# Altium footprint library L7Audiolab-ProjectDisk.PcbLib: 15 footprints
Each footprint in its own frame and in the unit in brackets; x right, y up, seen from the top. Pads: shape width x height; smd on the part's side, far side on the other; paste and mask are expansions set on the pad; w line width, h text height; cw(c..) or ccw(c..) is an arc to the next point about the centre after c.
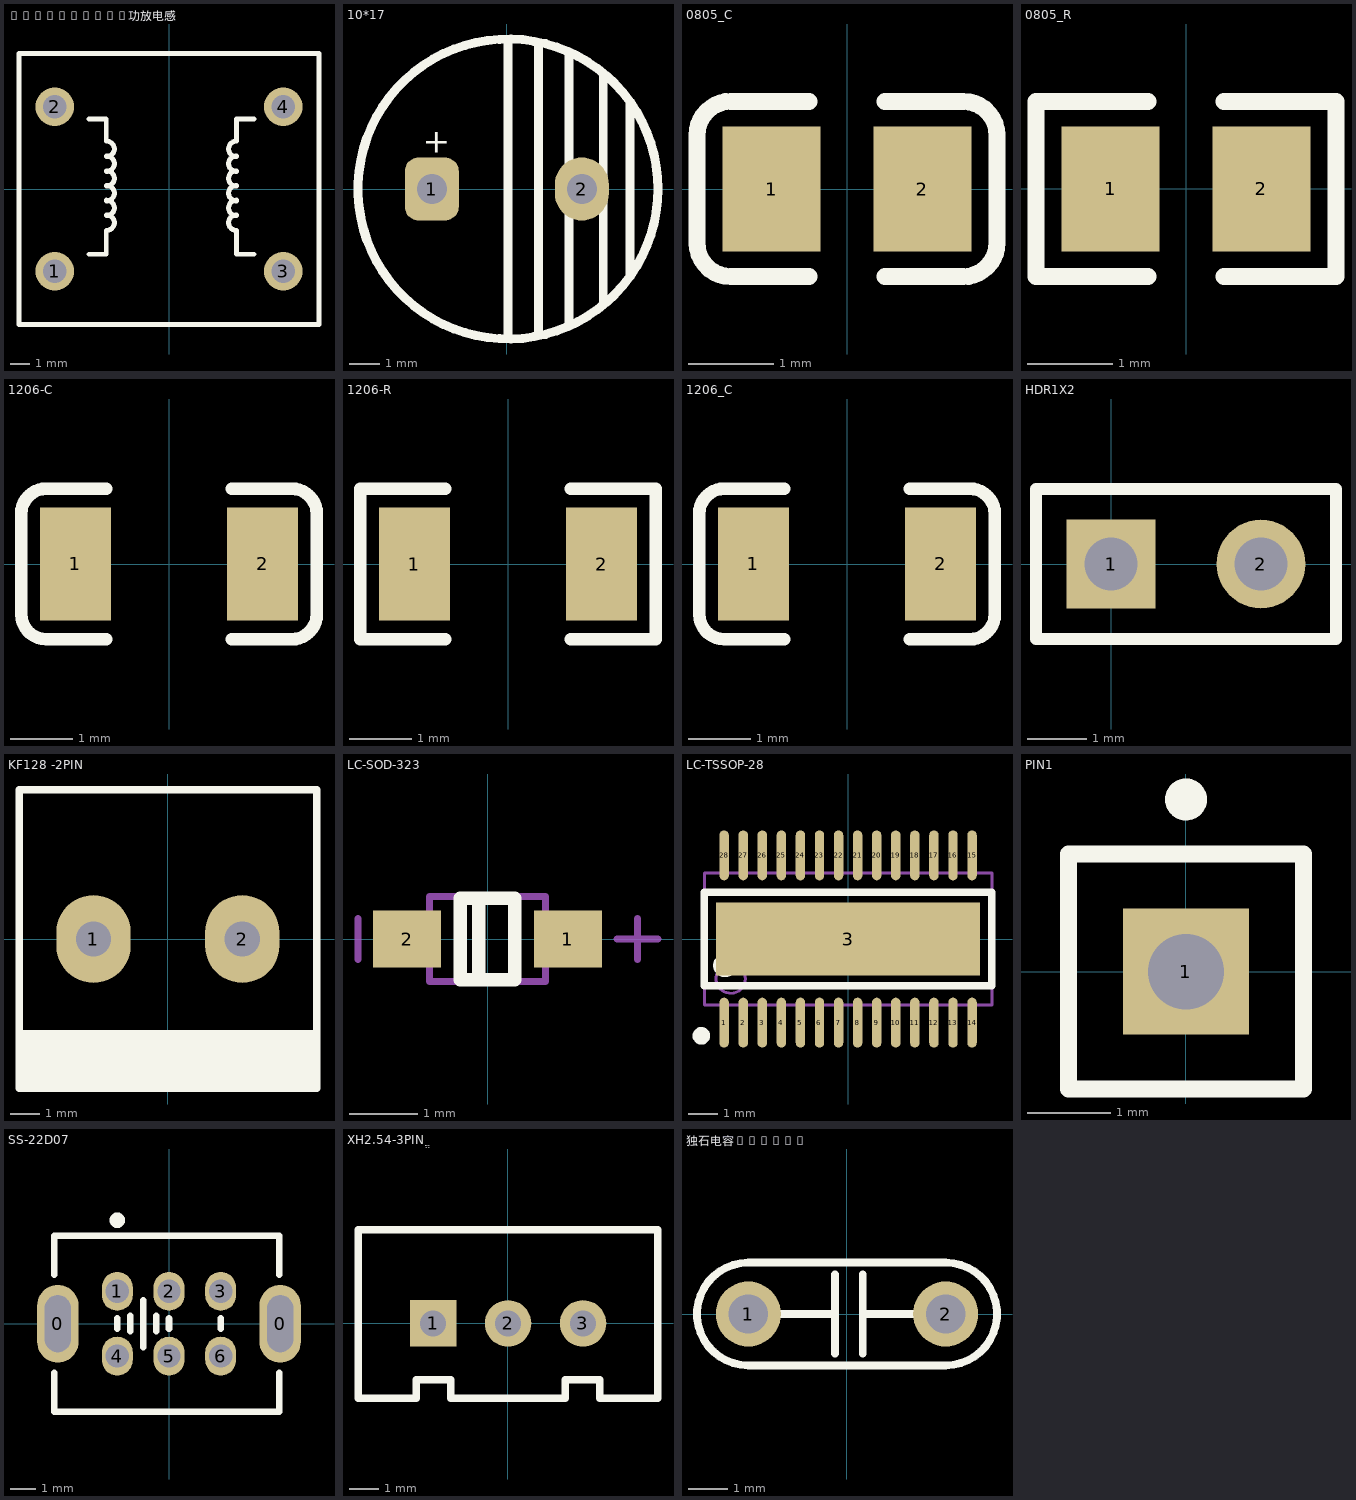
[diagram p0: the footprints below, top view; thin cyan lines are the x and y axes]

## 7W14A-100M功放电感 [mm]
pads (4):
  round 2 hole 1.2: 1(-5.9,-4.25) 2(-5.9,4.25) 3(5.9,-4.25) 4(5.9,4.25)
Top Overlay:
  lines w0.254: -4.129,-3.373 -3.24,-3.373 -3.24,-2.23 ; -4.129,3.612 -3.24,3.612 -3.24,2.469 cw(c-3.223,2.069) -3.242,1.67 ; -3.242,-2.14 ccw(c-3.223,-1.741) -3.24,-1.341 ; -3.242,-1.378 ccw(c-3.223,-0.979) -3.24,-0.579 ; -3.242,-0.616 ccw(c-3.223,-0.217) -3.24,0.183 ; -3.242,0.146 ccw(c-3.223,0.545) -3.24,0.945 ; -3.242,0.908 ccw(c-3.223,1.307) -3.24,1.707 ; 3.494,-2.23 3.494,-3.373 4.383,-3.373 ; 3.494,-1.341 ccw(c3.477,-1.741) 3.496,-2.14 ; 3.494,-0.579 ccw(c3.477,-0.979) 3.496,-1.378 ; 3.494,0.183 ccw(c3.477,-0.217) 3.496,-0.616 ; 3.494,0.945 ccw(c3.477,0.545) 3.496,0.146 ; 3.494,1.707 ccw(c3.477,1.307) 3.496,0.908 ; 3.496,1.67 cw(c3.477,2.069) 3.494,2.469 3.494,3.612 4.383,3.612 ; -7.75,-7 7.75,-7 7.75,7 -7.75,7 -7.75,-7

## 10*17 [mm] "插件电容50V/470UF"
height 1.14
pads (2):
  rrect50% 1.8x2.1 hole 1: 1(-2.5,0)
  oval 1.8x2.1 hole 1: 2(2.5,0)
Top Overlay:
  circle w0.3: c0.04,0 r5
  lines w0.3: 0.04,-4.974 0.04,4.956 ; 1.056,-4.826 1.056,4.836 ; 2.072,-4.536 2.072,4.572 ; 3.215,-3.804 3.215,3.84 ; 4.104,-2.921 4.104,2.886
  text "+" at -2.802,1.2 h0.8

## 0805_C [mm]
height 4.55
pads (2):
  rect 1.16x1.47 smd: 1(-0.89,0) 2(0.89,0)
Top Overlay:
  lines w0.2: -0.45,-1.035 -1.37,-1.035 cw(c-1.37,-0.635) -1.77,-0.635 -1.77,0.635 cw(c-1.37,0.635) -1.37,1.035 -0.45,1.035 ; 0.45,-1.035 1.37,-1.035 ccw(c1.37,-0.635) 1.77,-0.635 1.77,0.635 ccw(c1.37,0.635) 1.37,1.035 0.45,1.035
3D body: height 0.77, standoff -0.01, extent -1,-0.625 1.001,0.625

## 0805_R [mm]
pads (2):
  rect 1.16x1.47 smd: 1(-0.89,0) 2(0.89,0)
Top Overlay:
  lines w0.2: -0.45,-1.035 -1.77,-1.035 -1.77,1.035 -0.45,1.035 ; 0.45,-1.035 1.77,-1.035 1.77,1.035 0.45,1.035
3D body: height 0.49, standoff -0.01, extent -0.997,-0.625 1.003,0.625

## 1206-C [mm]
pads (2):
  rect 1.13x1.8 smd: 1(-1.49,0) 2(1.49,0)
Top Overlay:
  lines w0.2: -1,-1.2 -1.955,-1.2 cw(c-1.955,-0.8) -2.355,-0.8 -2.355,0.8 cw(c-1.955,0.8) -1.955,1.2 -1,1.2 ; 1,-1.2 1.955,-1.2 ccw(c1.955,-0.8) 2.355,-0.8 2.355,0.8 ccw(c1.955,0.8) 1.955,1.2 1,1.2
3D body: height 1, standoff 0, extent -1.602,-0.813 1.598,0.787

## 1206-R [mm] "1206贴片电阻"
height 1.14
pads (2):
  rect 1.13x1.8 smd: 1(-1.49,0) 2(1.49,0)
Top Overlay:
  lines w0.2: -1,-1.2 -2.355,-1.2 -2.355,1.2 -1,1.2 ; 1,-1.2 2.355,-1.2 2.355,1.2 1,1.2
3D body: height 0.85, standoff 0, extent -1.7,-0.864 1.65,0.866

## 1206_C [mm]
pads (2):
  rect 1.13x1.8 smd: 1(-1.49,0) 2(1.49,0)
Top Overlay:
  lines w0.2: -1,-1.2 -1.955,-1.2 cw(c-1.955,-0.8) -2.355,-0.8 -2.355,0.8 cw(c-1.955,0.8) -1.955,1.2 -1,1.2 ; 1,-1.2 1.955,-1.2 ccw(c1.955,-0.8) 2.355,-0.8 2.355,0.8 ccw(c1.955,0.8) 1.955,1.2 1,1.2
3D body: height 1, standoff 0, extent -1.602,-0.813 1.598,0.787

## HDR1X2 [mm] "Connector; Header; 2 Position"
height 1.14
pads (2):
  rect 1.5x1.5 hole 0.9: 1(0,0)
  round 1.5 hole 0.9: 2(2.54,0)
Top Overlay:
  lines w0.2: -1.27,-1.27 3.81,-1.27 3.81,1.27 -1.27,1.27 -1.27,-1.27

## KF128 -2PIN [mm] "5.08螺钉式PCB端子"
height 4.55
pads (2):
  oval 2.54x3 hole 1.2: 1(-2.54,0) 2(2.54,0)
Top Overlay:
  rectangle: -5.084,-5.04 5.162,-3.306
  lines w0.254: -5.08,5.1 -5.08,-5.1 5.08,-5.1 5.08,5.1 -5.078,5.1 ; -5.006,5.1 -4.982,5.1 ; -4.977,-4.423 -3.797,-3.243 ; -4.977,-3.243 5.05,-3.243 ; -3.726,-3.243 -3.721,-3.243 ; -3.652,-4.495 -2.4,-3.243 ; -2.331,-4.495 -1.079,-3.243 ; -1.112,-4.495 0.14,-3.243 ; 0.184,-4.495 1.435,-3.243 ; 1.384,-4.488 2.629,-3.243 ; 2.629,-4.488 3.873,-3.243

## LC-SOD-323 [mm]
height 1.14
pads (2):
  rect 1x0.83 smd: 1(1.18,0) 2(-1.18,0)
Top Overlay:
  lines w0.2: -0.13,-0.6 -0.13,0.6 ; -0.4,-0.6 0.4,-0.6 0.4,0.6 -0.4,0.6 -0.4,-0.6
Mechanical 13:
  lines w0.1: -0.85,-0.625 0.85,-0.625 0.85,0.625 -0.85,0.625 -0.85,-0.625
Mechanical 15:
  lines w0.1: -1.9,-0.3 -1.9,0.3 ; 1.9,0 2.5,0 ; 2.2,-0.3 2.2,0.3
3D body: height 1.1, standoff 0, extent -1.35,-0.625 1.35,0.625

## LC-TSSOP-28 [mm]
height 1.14
pads (29):
  oval 0.32x1.7 smd: 1(-4.225,-2.85) 2(-3.575,-2.85) 3(-2.925,-2.85) 4(-2.275,-2.85) 5(-1.625,-2.85) 6(-0.975,-2.85) 7(-0.325,-2.85) 8(0.325,-2.85) 9(0.975,-2.85) 10(1.625,-2.85) 11(2.275,-2.85) 12(2.925,-2.85) 13(3.575,-2.85) 14(4.225,-2.85) 15(4.225,2.85) 16(3.575,2.85) 17(2.925,2.85) 18(2.275,2.85) 19(1.625,2.85) 20(0.975,2.85) 21(0.325,2.85) 22(-0.325,2.85) 23(-0.975,2.85) 24(-1.625,2.85) 25(-2.275,2.85) 26(-2.925,2.85) 27(-3.575,2.85) 28(-4.225,2.85)
  rect 9x2.5 smd: 3(0,0)
Top Overlay:
  circle w0.3: c-5,-3.3 r0.15
  circle w0.4: c-4.2,-0.9 r0.2
  lines w0.254: -4.9,-1.6 -4.9,1.6 4.9,1.6 4.9,-1.6 -4.9,-1.6
Mechanical 13:
  circle w0.1: c-4,-1.35 r0.5
  lines w0.1: -4.9,-2.25 -4.9,2.25 4.9,2.25 4.9,-2.25 -4.9,-2.25

## PIN1 [mm] "Connector; Plug"
height 1.14
pads (1):
  rect 1.5x1.5 hole 0.9: 1(0,0)
Top Overlay:
  circle w0.25: c0,2.05 r0.125
  lines w0.2: -1.4,-1.4 -1.4,1.4 1.4,1.4 1.4,-1.4 -1.4,-1.4

## SS-22D07 [mm] "滑动开关"
pads (8):
  oval 1.6x3 hole 1 slot 2.2 at 90 deg: 0(-4.3,0) 0(4.3,0)
  oval 1.2x1.5 hole 0.9: 1(-2,1.25) 2(0,1.25) 3(2,1.25) 4(-2,-1.25) 5(0,-1.25) 6(2,-1.25)
Top Overlay:
  lines w0.254: -4.432,-1.9 -4.432,-3.4 4.268,-3.4 4.268,-1.9 ; -4.432,1.9 -4.432,3.4 4.268,3.4 4.268,1.9 ; -2,-0.2 -2,0.2 ; -1.5,-0.3 -1.5,0.3 ; -1,-0.9 -1,0.9 ; -0.5,-0.3 -0.5,0.3 ; 0,-0.2 0,0.2 ; 2,-0.2 2,0.2
  lines w0.3: -2.15,3.999 ccw(c-2,4) -2.15,4.001

## XH2.54-3PINֱ [mil]
pads (3):
  rect 62x62 hole 34.65: 1(-100,0)
  round 62 hole 34.65: 2(0,0) 3(100,0)
Top Overlay:
  lines w10: -200,-100 -175,-100 -122.2,-100 -122.2,-75 -76.38,-75 -76.38,-100 76.38,-100 76.38,-75 122.2,-75 122.2,-100 175,-100 200,-100 200,-75 200,100 200,125 -200,125 -200,100 -200,-75 -200,-100
3D body: height 276.77, standoff -97.24, extent -198.43,-94.49 198.43,129.92

## 独石电容5.08MM [mm] "独石电容5.08MM"
height 1.14
pads (2):
  round 1.65 hole 1: 1(-2.5,0) 2(2.5,0)
Top Overlay:
  lines w0.2: -2.5,0 -1.5,0 -0.9,0 -0.4,0 ; -0.3,-1 -0.3,1 -0.3,0 ; 0.4,-1 0.4,1 0.4,0 0.9,0 1.5,0 2.5,0 ; -2.5,-1.3 cw(c-2.5,0) -2.5,1.3 2.5,1.3 cw(c2.5,0) 2.5,-1.3 -2.5,-1.3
